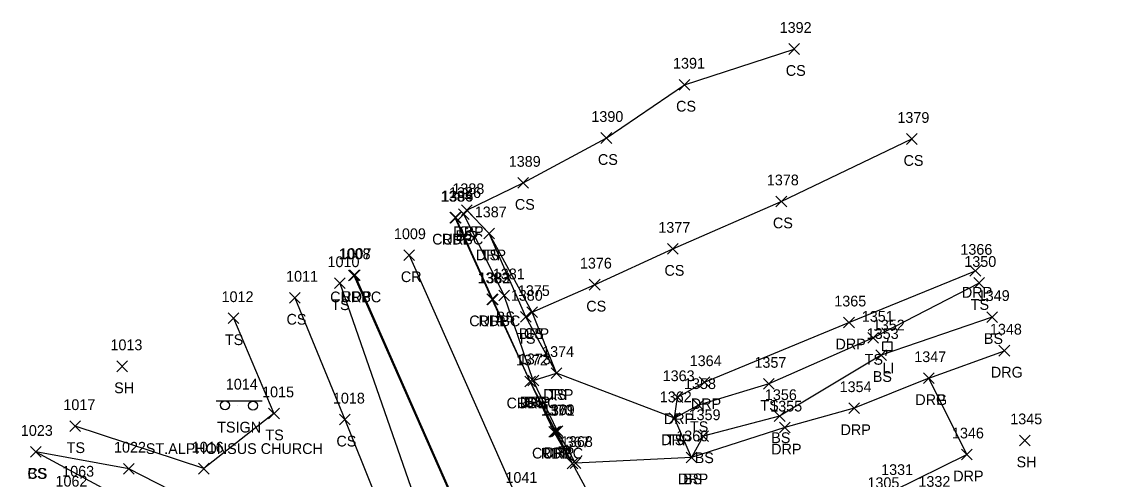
# Model space of a CAD drawing. Extents: x 1504228 to 1506103, y 437717 to 440106.
# Drawn here: x 1505006.9 to 1505211.7, y 438441.9 to 438527 of the extents above; entities that cross this region are included whole.
import ezdxf

# ---------------------------------------------------------------- set-up
doc = ezdxf.new("R2010")
doc.units = 0
for name, color, linetype in [('L_A', 7, 'Continuous'), ('L_I', 7, 'Continuous'), ('L_TIC', 7, 'Continuous'), ('LELB', 7, 'Continuous'), ('P_A', 7, 'Continuous'), ('P_I', 7, 'Continuous'), ('P_TIC', 7, 'Continuous'), ('PET', 7, 'Continuous'), ('PRC', 7, 'Continuous'), ('R_A', 7, 'Continuous'), ('R_I', 7, 'Continuous'), ('R_TIC', 7, 'Continuous'), ('RC', 7, 'Continuous'), ('RDG', 7, 'Continuous'), ('RDP', 7, 'Continuous'), ('S_A', 7, 'Continuous'), ('S_C', 7, 'Continuous'), ('S_I', 7, 'Continuous'), ('SSGN', 7, 'Continuous'), ('U_A', 7, 'Continuous'), ('U_I', 7, 'Continuous'), ('ULP', 7, 'Continuous')]:
    doc.layers.add(name, color=color, linetype=linetype)

msp = doc.modelspace()

# ---------------------------------------------------------------- linework, layer by layer
at = {"layer": 'L_TIC'}
for points in [[(1505149.76, 438520.94), (1505151.76, 438522.94)], [(1505151.76, 438520.94), (1505149.76, 438522.94)], [(1505129.33, 438514.29), (1505131.33, 438516.29)], [(1505131.33, 438514.29), (1505129.33, 438516.29)], [(1505114.77, 438504.37), (1505116.77, 438506.37)], [(1505116.77, 438504.37), (1505114.77, 438506.37)], [(1505171.7, 438504.19), (1505173.7, 438506.19)], [(1505173.7, 438504.19), (1505171.7, 438506.19)], [(1505099.3, 438496.02), (1505101.3, 438498.02)], [(1505101.3, 438496.02), (1505099.3, 438498.02)], [(1505147.37, 438492.56), (1505149.37, 438494.56)], [(1505149.37, 438492.56), (1505147.37, 438494.56)], [(1505088.23, 438490.21), (1505090.23, 438492.21)], [(1505090.23, 438490.21), (1505088.23, 438492.21)], [(1505088.78, 438490.93), (1505090.78, 438492.93)], [(1505090.78, 438490.93), (1505088.78, 438492.93)], [(1505092.96, 438486.61), (1505094.96, 438488.61)], [(1505094.96, 438486.61), (1505092.96, 438488.61)], [(1505127.16, 438483.73), (1505129.16, 438485.73)], [(1505129.16, 438483.73), (1505127.16, 438485.73)], [(1505065.13, 438477.34), (1505067.13, 438479.34)], [(1505067.13, 438477.34), (1505065.13, 438479.34)], [(1505112.6, 438477.07), (1505114.6, 438479.07)], [(1505114.6, 438477.07), (1505112.6, 438479.07)], [(1505184.24, 438477.38), (1505186.24, 438479.38)], [(1505186.24, 438477.38), (1505184.24, 438479.38)], [(1505056.76, 438474.63), (1505058.76, 438476.63)], [(1505058.76, 438474.63), (1505056.76, 438476.63)], [(1505095.75, 438475.07), (1505097.75, 438477.07)], [(1505097.75, 438475.07), (1505095.75, 438477.07)], [(1505100.98, 438471.96), (1505102.98, 438473.96)], [(1505102.98, 438471.96), (1505100.98, 438473.96)], [(1505045.31, 438470.83), (1505047.31, 438472.83)], [(1505047.31, 438470.83), (1505045.31, 438472.83)], [(1505099.76, 438471.08), (1505101.76, 438473.08)], [(1505101.76, 438471.08), (1505099.76, 438473.08)], [(1505186.66, 438471.04), (1505188.66, 438473.04)], [(1505188.66, 438471.04), (1505186.66, 438473.04)], [(1505164.49, 438467.17), (1505166.49, 438469.17)], [(1505166.49, 438467.17), (1505164.49, 438469.17)], [(1505165.97, 438463.97), (1505167.97, 438465.97)], [(1505167.97, 438463.97), (1505165.97, 438465.97)], [(1505024.6, 438461.87), (1505026.6, 438463.87)], [(1505026.6, 438461.87), (1505024.6, 438463.87)], [(1505105.51, 438460.62), (1505107.51, 438462.62)], [(1505107.51, 438460.62), (1505105.51, 438462.62)], [(1505101.17, 438459.25), (1505103.17, 438461.25)], [(1505103.17, 438459.25), (1505101.17, 438461.25)], [(1505145.07, 438458.6), (1505147.07, 438460.6)], [(1505147.07, 438458.6), (1505145.07, 438460.6)], [(1505131.94, 438454.64), (1505133.94, 438456.64)], [(1505133.94, 438454.64), (1505131.94, 438456.64)], [(1505052.86, 438453.1), (1505054.86, 438455.1)], [(1505054.86, 438453.1), (1505052.86, 438455.1)], [(1505066.05, 438451.95), (1505068.05, 438453.95)], [(1505068.05, 438451.95), (1505066.05, 438453.95)], [(1505127.47, 438452.19), (1505129.47, 438454.19)], [(1505129.47, 438452.19), (1505127.47, 438454.19)], [(1505147.06, 438452.59), (1505149.06, 438454.59)], [(1505149.06, 438452.59), (1505147.06, 438454.59)], [(1505015.84, 438450.73), (1505017.84, 438452.73)], [(1505017.84, 438450.73), (1505015.84, 438452.73)], [(1505132.8, 438448.85), (1505134.8, 438450.85)], [(1505134.8, 438448.85), (1505132.8, 438450.85)], [(1505192.72, 438448.08), (1505194.72, 438450.08)], [(1505194.72, 438448.08), (1505192.72, 438450.08)], [(1505008.49, 438445.93), (1505010.49, 438447.93)], [(1505010.49, 438445.93), (1505008.49, 438447.93)], [(1505008.49, 438445.93), (1505010.49, 438447.93)], [(1505010.49, 438445.93), (1505008.49, 438447.93)], [(1505109.05, 438443.86), (1505111.05, 438445.86)], [(1505111.05, 438443.86), (1505109.05, 438445.86)], [(1505130.63, 438444.91), (1505132.63, 438446.91)], [(1505132.63, 438444.91), (1505130.63, 438446.91)], [(1505025.83, 438442.8), (1505027.83, 438444.8)], [(1505027.83, 438442.8), (1505025.83, 438444.8)], [(1505039.8, 438442.82), (1505041.8, 438444.82)], [(1505041.8, 438442.82), (1505039.8, 438444.82)]]:
    msp.add_lwpolyline(points, dxfattribs=at)
at = {"layer": 'LELB'}
for points in [[(1505089.78, 438491.93), (1505100.3, 438497.02), (1505115.77, 438505.37), (1505130.33, 438515.29), (1505150.76, 438521.94)], [(1505101.98, 438472.96), (1505113.6, 438478.07), (1505128.16, 438484.73), (1505148.37, 438493.56), (1505172.7, 438505.19)], [(1505102.17, 438460.25), (1505096.75, 438476.07), (1505089.23, 438491.21)], [(1505185.24, 438478.38), (1505165.49, 438468.17), (1505146.07, 438459.6), (1505132.94, 438455.64), (1505128.47, 438453.19), (1505106.51, 438461.62), (1505100.76, 438472.08), (1505093.96, 438487.61)], [(1505066.13, 438478.34), (1505082.79, 438430.57), (1505090.38, 438412.27), (1505093.43, 438405.26), (1505092.12, 438400.75), (1505084.32, 438400.96), (1505068.59, 438407.1), (1505055.45, 438414.73), (1505017.23, 438439.34)], [(1505057.76, 438475.63), (1505067.05, 438452.95), (1505078.01, 438425.75), (1505068.86, 438419.51), (1505047.43, 438433.25), (1505026.83, 438443.8), (1505009.49, 438446.93)], [(1505046.31, 438471.83), (1505053.86, 438454.1), (1505040.8, 438443.82), (1505016.84, 438451.73)], [(1505187.66, 438472.04), (1505166.97, 438464.97), (1505148.06, 438453.59), (1505133.8, 438449.85), (1505131.63, 438445.91), (1505110.05, 438444.86)], [(1505009.49, 438446.93), (1505034.88, 438433.26), (1505059.13, 438418.39), (1505073.11, 438411.36), (1505084.65, 438408.25), (1505088.77, 438405.58), (1505088.5, 438402.9), (1505084.32, 438400.96)]]:
    msp.add_lwpolyline(points, dxfattribs=at)
at = {"layer": 'P_TIC'}
for points in [[(1505086.61, 438489.54), (1505088.61, 438491.54)], [(1505088.61, 438489.54), (1505086.61, 438491.54)], [(1505078.07, 438482.55), (1505080.07, 438484.55)], [(1505080.07, 438482.55), (1505078.07, 438484.55)], [(1505067.91, 438478.86), (1505069.91, 438480.86)], [(1505069.91, 438478.86), (1505067.91, 438480.86)], [(1505093.49, 438474.34), (1505095.49, 438476.34)], [(1505095.49, 438474.34), (1505093.49, 438476.34)], [(1505100.61, 438459.04), (1505102.61, 438461.04)], [(1505102.61, 438459.04), (1505100.61, 438461.04)], [(1505105.08, 438449.67), (1505107.08, 438451.67)], [(1505107.08, 438449.67), (1505105.08, 438451.67)], [(1505108.45, 438443.78), (1505110.45, 438445.78)], [(1505110.45, 438443.78), (1505108.45, 438445.78)]]:
    msp.add_lwpolyline(points, dxfattribs=at)
at = {"layer": 'PET'}
msp.add_lwpolyline([(1505068.91, 438479.86), (1505088.8, 438434.79), (1505098.18, 438413.38), (1505109.54, 438384.97), (1505120.75, 438360.59), (1505130.11, 438339.58), (1505143.01, 438310.87), (1505160.43, 438272.1), (1505181.32, 438230.83), (1505199.45, 438238.76), (1505211.65, 438244.29), (1505203.78, 438257.46), (1505193.87, 438276.08), (1505183.09, 438301.1), (1505168.27, 438329), (1505148.65, 438369.04), (1505141.29, 438386.17), (1505109.45, 438444.78), (1505106.08, 438450.67), (1505101.61, 438460.04), (1505094.49, 438475.34), (1505087.61, 438490.54)], dxfattribs=at)
at = {"layer": 'PRC'}
msp.add_lwpolyline([(1505079.07, 438483.55), (1505099.19, 438438.18), (1505118.7, 438394.37), (1505142.43, 438344.29), (1505155.62, 438317.19), (1505174.86, 438280.77), (1505189.02, 438255.49), (1505199.45, 438238.76)], dxfattribs=at)
at = {"layer": 'R_TIC'}
for points in [[(1505088.78, 438490.93), (1505090.78, 438492.93)], [(1505090.78, 438490.93), (1505088.78, 438492.93)], [(1505086.75, 438489.54), (1505088.75, 438491.54)], [(1505088.75, 438489.54), (1505086.75, 438491.54)], [(1505092.96, 438486.61), (1505094.96, 438488.61)], [(1505094.96, 438486.61), (1505092.96, 438488.61)], [(1505067.75, 438478.79), (1505069.75, 438480.79)], [(1505069.75, 438478.79), (1505067.75, 438480.79)], [(1505183.52, 438479.64), (1505185.52, 438481.64)], [(1505185.52, 438479.64), (1505183.52, 438481.64)], [(1505093.65, 438474.33), (1505095.65, 438476.33)], [(1505095.65, 438474.33), (1505093.65, 438476.33)], [(1505100.98, 438471.96), (1505102.98, 438473.96)], [(1505102.98, 438471.96), (1505100.98, 438473.96)], [(1505159.98, 438470.02), (1505161.98, 438472.02)], [(1505161.98, 438470.02), (1505159.98, 438472.02)], [(1505188.92, 438464.78), (1505190.92, 438466.78)], [(1505190.92, 438464.78), (1505188.92, 438466.78)], [(1505105.51, 438460.62), (1505107.51, 438462.62)], [(1505107.51, 438460.62), (1505105.51, 438462.62)], [(1505174.84, 438459.66), (1505176.84, 438461.66)], [(1505176.84, 438459.66), (1505174.84, 438461.66)], [(1505174.84, 438459.66), (1505176.84, 438461.66)], [(1505176.84, 438459.66), (1505174.84, 438461.66)], [(1505100.61, 438459.04), (1505102.61, 438461.04)], [(1505102.61, 438459.04), (1505100.61, 438461.04)], [(1505101.17, 438459.25), (1505103.17, 438461.25)], [(1505103.17, 438459.25), (1505101.17, 438461.25)], [(1505133.04, 438458.91), (1505135.04, 438460.91)], [(1505135.04, 438458.91), (1505133.04, 438460.91)], [(1505128.01, 438456.11), (1505130.01, 438458.11)], [(1505130.01, 438456.11), (1505128.01, 438458.11)], [(1505160.93, 438454.07), (1505162.93, 438456.07)], [(1505162.93, 438454.07), (1505160.93, 438456.07)], [(1505127.47, 438452.19), (1505129.47, 438454.19)], [(1505129.47, 438452.19), (1505127.47, 438454.19)], [(1505105.35, 438449.71), (1505107.35, 438451.71)], [(1505107.35, 438449.71), (1505105.35, 438451.71)], [(1505105.67, 438449.79), (1505107.67, 438451.79)], [(1505107.67, 438449.79), (1505105.67, 438451.79)], [(1505148.01, 438450.46), (1505150.01, 438452.46)], [(1505150.01, 438450.46), (1505148.01, 438452.46)], [(1505181.91, 438445.45), (1505183.91, 438447.45)], [(1505183.91, 438445.45), (1505181.91, 438447.45)], [(1505108.45, 438443.78), (1505110.45, 438445.78)], [(1505110.45, 438443.78), (1505108.45, 438445.78)], [(1505109.05, 438443.86), (1505111.05, 438445.86)], [(1505111.05, 438443.86), (1505109.05, 438445.86)], [(1505130.63, 438444.91), (1505132.63, 438446.91)], [(1505132.63, 438444.91), (1505130.63, 438446.91)]]:
    msp.add_lwpolyline(points, dxfattribs=at)
at = {"layer": 'RC'}
for points in [[(1505109.45, 438444.78), (1505106.35, 438450.71), (1505101.61, 438460.04), (1505094.65, 438475.33), (1505087.75, 438490.54)], [(1505068.75, 438479.79), (1505088.67, 438434.66), (1505097.76, 438413.11), (1505097.28, 438406.44), (1505096.05, 438402.75), (1505093.44, 438399.46)]]:
    msp.add_lwpolyline(points, dxfattribs=at)
at = {"layer": 'RDG'}
msp.add_lwpolyline([(1505175.84, 438460.66), (1505189.92, 438465.78)], dxfattribs=at)
at = {"layer": 'RDP'}
for points in [[(1505110.05, 438444.86), (1505106.67, 438450.79), (1505102.17, 438460.25), (1505106.51, 438461.62), (1505101.98, 438472.96), (1505093.96, 438487.61), (1505089.78, 438491.93)], [(1505141.29, 438386.17), (1505139.71, 438394.63), (1505136.48, 438403.18), (1505136.74, 438412.41), (1505143.52, 438419.88), (1505153.08, 438431.81), (1505169.09, 438439.64), (1505182.91, 438446.45), (1505175.84, 438460.66), (1505161.93, 438455.07), (1505149.01, 438451.46), (1505131.63, 438445.91), (1505128.47, 438453.19), (1505129.01, 438457.11), (1505134.04, 438459.91), (1505160.98, 438471.02), (1505184.52, 438480.64)]]:
    msp.add_lwpolyline(points, dxfattribs=at)
at = {"layer": 'SSGN'}
for p, q in [((1505043.08, 438456.47), (1505051.67, 438456.47)), ((1505047.1, 438455.56), (1505047.1, 438455.56))]:
    msp.add_line(p, q, dxfattribs=at)
for centre in [(1505044.74, 438455.63), (1505049.95, 438455.56)]:
    msp.add_circle(centre, 0.833, dxfattribs=at)
at = {"layer": 'ULP'}
for p, q in [((1505168.28, 438468.23), (1505168.11, 438467.4)), ((1505167.28, 438465.73), (1505167.28, 438467.4)), ((1505167.28, 438467.4), (1505168.95, 438467.4)), ((1505168.95, 438465.73), (1505167.28, 438465.73)), ((1505167.86, 438464.9), (1505168.11, 438465.73)), ((1505168.11, 438466.56), (1505168.11, 438466.56)), ((1505168.95, 438467.4), (1505168.95, 438465.73))]:
    msp.add_line(p, q, dxfattribs=at)

# ---------------------------------------------------------------- texts
at = {"layer": 'L_A'}
for s, p in [('CS', (1505149.2, 438516.94)), ('CS', (1505128.77, 438510.29)), ('CS', (1505114.21, 438500.37)), ('CS', (1505171.14, 438500.19)), ('CS', (1505098.74, 438492.02)), ('CS', (1505146.81, 438488.56)), ('BS', (1505087.67, 438486.21)), ('CS', (1505088.23, 438486.93)), ('TS', (1505092.37, 438482.61)), ('CS', (1505126.6, 438479.73)), ('TS', (1505064.54, 438473.34)), ('CS', (1505112.04, 438473.07)), ('TS', (1505183.65, 438473.38)), ('CS', (1505056.2, 438470.63)), ('BS', (1505095.19, 438471.07)), ('CS', (1505100.42, 438467.96)), ('TS', (1505044.72, 438466.83)), ('TS', (1505099.17, 438467.08)), ('BS', (1505186.1, 438467.04)), ('TS', (1505163.9, 438463.17)), ('BS', (1505165.41, 438459.97)), ('SH', (1505024.09, 438457.87)), ('BS', (1505100.61, 438455.25)), ('TS', (1505104.92, 438456.62)), ('TS', (1505144.48, 438454.6)), ('TS', (1505052.27, 438449.1)), ('TS', (1505131.35, 438450.64)), ('CS', (1505065.49, 438447.95)), ('TS', (1505126.88, 438448.19)), ('BS', (1505146.5, 438448.59)), ('TS', (1505015.25, 438446.73)), ('BS', (1505132.24, 438444.85)), ('SH', (1505192.2, 438444.08)), ('CS', (1505007.93, 438441.93)), ('BS', (1505007.93, 438441.93)), ('BS', (1505130.07, 438440.91))]:
    msp.add_text(s, height=2, dxfattribs=at).set_placement(p)
at = {"layer": 'L_I'}
for s, p in [('1392', (1505148.06, 438524.94)), ('1391', (1505128.2, 438518.29)), ('1390', (1505112.99, 438508.37)), ('1379', (1505170, 438508.19)), ('1389', (1505097.6, 438500.02)), ('1378', (1505145.68, 438496.56)), ('1386', (1505086.48, 438494.21)), ('1388', (1505087.09, 438494.93)), ('1387', (1505091.27, 438490.61)), ('1377', (1505125.46, 438487.73)), ('1010', (1505063.84, 438481.34)), ('1376', (1505110.85, 438481.07)), ('1350', (1505182.46, 438481.38)), ('1011', (1505056.12, 438478.63)), ('1381', (1505094.63, 438479.07)), ('1375', (1505099.29, 438475.96)), ('1012', (1505044.1, 438474.83)), ('1380', (1505097.98, 438475.08)), ('1349', (1505184.96, 438475.04)), ('1351', (1505163.36, 438471.17)), ('1353', (1505164.28, 438467.97)), ('1013', (1505023.4, 438465.87)), ('1374', (1505103.82, 438464.62)), ('1373', (1505099.48, 438463.25)), ('1357', (1505143.37, 438462.6)), ('1358', (1505130.24, 438458.64)), ('1015', (1505051.65, 438457.1)), ('1018', (1505064.84, 438455.95)), ('1362', (1505125.73, 438456.19)), ('1356', (1505145.31, 438456.59)), ('1017', (1505014.63, 438454.73)), ('1359', (1505131.1, 438452.85)), ('1345', (1505191.02, 438452.08)), ('1023', (1505006.71, 438449.93)), ('1023', (1505006.71, 438449.93)), ('1368', (1505107.31, 438447.86)), ('1360', (1505128.8, 438448.91)), ('1022', (1505024.06, 438446.8)), ('1016', (1505038.54, 438446.82)), ('1063', (1505014.41, 438442.34)), ('1305', (1505164.42, 438440.21))]:
    msp.add_text(s, height=2, dxfattribs=at).set_placement(p)
at = {"layer": 'P_A'}
for s, p in [('RDP', (1505085.1, 438485.54)), ('CR', (1505077.5, 438478.55)), ('RDP', (1505066.4, 438474.86)), ('RDP', (1505091.97, 438470.34)), ('RDP', (1505099.1, 438455.04)), ('RDP', (1505103.57, 438445.67))]:
    msp.add_text(s, height=2, dxfattribs=at).set_placement(p)
at = {"layer": 'P_I'}
for s, p in [('1384', (1505084.92, 438493.54)), ('1009', (1505076.21, 438486.55)), ('1007', (1505066.06, 438482.86)), ('1383', (1505091.79, 438478.34)), ('1372', (1505098.92, 438463.04)), ('1371', (1505103.96, 438453.67)), ('1367', (1505106.71, 438447.78)), ('1041', (1505096.98, 438441.18)), ('1062', (1505013.16, 438440.48))]:
    msp.add_text(s, height=2, dxfattribs=at).set_placement(p)
at = {"layer": 'R_A'}
for s, p in [('DRP', (1505087.27, 438486.93)), ('CURBC', (1505083.33, 438485.54)), ('DRP', (1505091.45, 438482.61)), ('CURBC', (1505064.33, 438474.79)), ('DRP', (1505182.01, 438475.64)), ('CURBC', (1505090.24, 438470.33)), ('DRP', (1505099.47, 438467.96)), ('DRP', (1505158.47, 438466.02)), ('DRG', (1505187.41, 438460.78)), ('DRP', (1505099.66, 438455.25)), ('DRP', (1505104, 438456.62)), ('DRG', (1505173.33, 438455.66)), ('DRP', (1505173.33, 438455.66)), ('CURBC', (1505097.19, 438455.04)), ('DRP', (1505131.52, 438454.91)), ('DRP', (1505126.5, 438452.11)), ('DRP', (1505159.41, 438450.07)), ('DRP', (1505125.96, 438448.19)), ('CURBC', (1505101.93, 438445.71)), ('DRP', (1505104.16, 438445.79)), ('DRP', (1505146.49, 438446.46)), ('DRP', (1505129.12, 438440.91)), ('DRP', (1505180.4, 438441.45))]:
    msp.add_text(s, height=2, dxfattribs=at).set_placement(p)
at = {"layer": 'R_I'}
for s, p in [('1388', (1505087.09, 438494.93)), ('1385', (1505085.05, 438493.54)), ('1387', (1505091.27, 438490.61)), ('1008', (1505065.9, 438482.79)), ('1366', (1505181.73, 438483.64)), ('1382', (1505091.96, 438478.33)), ('1375', (1505099.29, 438475.96)), ('1365', (1505158.24, 438474.02)), ('1348', (1505187.23, 438468.78)), ('1374', (1505103.82, 438464.62)), ('1347', (1505173.14, 438463.66)), ('1347', (1505173.14, 438463.66)), ('1372', (1505098.92, 438463.04)), ('1373', (1505099.48, 438463.25)), ('1364', (1505131.3, 438462.91)), ('1363', (1505126.27, 438460.11)), ('1354', (1505159.23, 438458.07)), ('1362', (1505125.73, 438456.19)), ('1370', (1505103.57, 438453.71)), ('1369', (1505103.92, 438453.79)), ('1355', (1505146.31, 438454.46)), ('1346', (1505180.16, 438449.45)), ('1367', (1505106.71, 438447.78)), ('1368', (1505107.31, 438447.86)), ('1360', (1505128.8, 438448.91)), ('1331', (1505166.97, 438442.64)), ('1331', (1505166.97, 438442.64)), ('1332', (1505173.91, 438440.44))]:
    msp.add_text(s, height=2, dxfattribs=at).set_placement(p)
at = {"layer": 'S_A'}
msp.add_text('TSIGN', height=2, dxfattribs=at).set_placement((1505043.28, 438450.55))
at = {"layer": 'S_C'}
msp.add_text('ST.ALPHONSUS CHURCH', height=2, dxfattribs=at).set_placement((1505029.99, 438446.55))
at = {"layer": 'S_I'}
msp.add_text('1014', height=2, dxfattribs=at).set_placement((1505044.89, 438458.55))
at = {"layer": 'U_A'}
msp.add_text('LI', height=2, dxfattribs=at).set_placement((1505167.21, 438461.56))
at = {"layer": 'U_I'}
msp.add_text('1352', height=2, dxfattribs=at).set_placement((1505165.42, 438469.56))

doc.saveas('drawing.dxf')
